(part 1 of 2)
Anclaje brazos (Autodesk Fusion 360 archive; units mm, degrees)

design "Anclaje brazos" references "Anillos_cuerpo_baimax", "pilares_anillos_baimax"
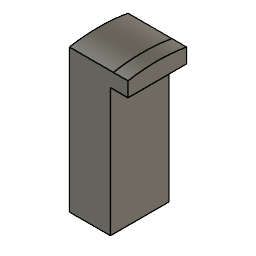
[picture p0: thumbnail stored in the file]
part number: 2026-07-14-14-53-27-253
component_insert "Inserción de componente1"
component_insert "Inserción de componente2"
position "Posición1"
component_insert "Inserción de componente3"
component_insert "Inserción de componente4"
component_insert "Inserción de componente5"
position "Posición2"
sketch "Boceto1" plane through (0, 0, 91.5) normal (0, 0, 1) x axis (1, 0, 0)
  line L1 (1.5, 3) -> (0, 3)
  line L2 (1.5, 0) -> (1.5, 3)
  line L3 (-1.5, 0) -> (1.5, 0)
  line L4 (-1.5, 3) -> (-1.5, 0)
  line L5 (0, 3) -> (-1.5, 3)
  circle C1 centre (0, 1.5) radius 21
  circle C2 centre (0, 1.5) radius 22.75
  circle C3 centre (0, 1.5) radius 5
  point P2 (0, 1.5)
  point P4 (0, 3)
  point P5 (1.5, 3)
  point P6 (1.5, 0)
  point P7 (-1.5, 0)
  point P8 (-1.5, 3)
  concentric C1 C3
  perpendicular L1 L2
  perpendicular L2 L3
  perpendicular L3 L4
  dimension "d1" diameter C3 = 10
  dimension "d2" distance P2 P4 = 1.5
  dimension "d3" distance P4 P5 = 1.5
  dimension "d4" distance P5 P6 = 3
  dimension "d5" distance P6 P7 = 3
  dimension "d6" distance P7 P8 = 3
extrude "Extruir1" new body sketch "Boceto1" profile of L1 L2 L3 L4 L5 along normal blind 7
position "Posición3"
work_plane "PlanoDeObra1" Distance 0
work_plane "PlanoDeObra2" Distance 0
work_plane "PlanoDeObra3" Distance 0
work_plane "PlanoDeObra4" Distance 0
work_plane "PlanoDeObra5" Distance 0
sketch "Boceto2" plane through (-13.1366, 0, 8.8009) normal (-0.8308, 0, 0.5566) x axis (0.5566, 0, 0.8308)
  curve K1 (76.8647, 1.5) -> (74.8126, 1.5)
  curve K2 (75.8387, 7.5) -> (75.8387, -4.5)
  closed curve K3 centre (75.8387, 1.5)
  point P3 (74.8126, 1.5)
  point P4 (76.8647, 1.5)
  point P5 (75.8387, -4.5)
  point P6 (75.8387, 7.5)
  coincident K3 P3
  coincident K3 P4
  coincident K3 P5
  coincident K3 P6
  dimension "d16" = 12
sketch "Boceto3" plane through (-12.068, 0, 51.9927) normal (-0.2261, 0, 0.9741) x axis (0.9741, 0, 0.2261)
  line L1 (52.6699, 3) -> (52.5037, 3)
  line L2 (52.6699, 0) -> (52.5037, 0)
  line L3 (52.6699, 3) -> (52.6699, 0)
  line L4 (53.6699, 1.5) -> (52.6699, 1.5)
  curve K1 (59.1661, 7.4335) -> (59.1661, -4.4335)
  closed curve K2 centre (59.1661, 1.5)
  point P5 (52.6699, 0)
  point P6 (52.6699, 0)
  point P3 (52.6699, 3)
  point P7 (52.6699, 3)
  point P8 (52.6699, 1.5)
  point P11 (59.1661, -4.4335)
  point P12 (59.1661, 7.4335)
  point P9 (53.6699, 1.5)
  coincident P5 P6
  coincident P3 P7
  midpoint L3 P8
  perpendicular L3 L4
  coincident K2 P11
  coincident K2 P12
  dimension "d17" distance P8 P9 = 1
work_plane "PlanoDeObra7" Distance 0
sketch "Boceto4" plane through (37.3705, 0, 0) normal (-1, 0, 0) x axis (0, -1, 0)
  curve K1 (-7.5, 70.5259) -> (4.5, 70.5259)
  curve K2 (-1.5, 67.3726) -> (-1.5, 73.6792)
  closed curve K3 centre (-1.5, 70.5259)
  point P3 (4.5, 70.5259)
  point P4 (-7.5, 70.5259)
  point P5 (-1.5, 73.6792)
  point P6 (-1.5, 67.3726)
  coincident K3 P3
  coincident K3 P4
  coincident K3 P5
  coincident K3 P6
  dimension "d20" distance K3 = 12
sketch "Boceto5" plane through (-0.1048, 0, 0.1825) normal (-0.4982, 0, 0.8671) x axis (0.8671, 0, 0.4982)
  line L1 (53.2165, 0) -> (53.2165, 3)
sketch "Boceto6" plane through (9.9891, 0, -18.2801) normal (-0.4795, 0, 0.8775) x axis (0.8775, 0, 0.4795)
  line L1 (49.7075, 0) -> (49.7075, 3)
  curve K1 (59.1923, 13.5) -> (59.1923, -10.5)
  curve K2 (49.7954, 1.5) -> (68.5892, 1.5)
  closed curve K3 centre (59.1923, 1.5)
  point P5 (59.1923, -10.5)
  point P6 (59.1923, 13.5)
  point P7 (68.5892, 1.5)
  point P8 (49.7954, 1.5)
  coincident K3 P5
  coincident K3 P6
  coincident K3 P7
  coincident K3 P8
  dimension "d36" = 20
sketch "Boceto7" plane through (2.1859, 0, 8.3402) normal (0.2535, 0, 0.9673) x axis (0.9673, 0, -0.2535)
  line L1 (54.1489, 3) -> (54.1489, 0)
  curve K1 (64.3232, 16.5) -> (64.3232, -13.5)
  curve K2 (77.3232, 1.5) -> (51.3232, 1.5)
  closed curve K3 centre (64.3232, 1.5)
  point P5 (64.3232, -13.5)
  point P6 (64.3232, 16.5)
  point P7 (51.3232, 1.5)
  point P8 (77.3232, 1.5)
  coincident K3 P5
  coincident K3 P6
  coincident K3 P7
  coincident K3 P8
  vertical K1
  dimension "d40" distance K3 = 30
  dimension "d41" = 26
work_plane "PlanoDeObra8" Distance 0
sketch "Boceto8" plane through (0, 0, 60.2768) normal (0, 0, 1) x axis (1, 0, 0)
work_plane "PlanoDeObra10" sketch "Boceto4" + "Boceto3"
sketch "Boceto9" plane through (-4.7545, 0, 3.4501) normal (-0.8094, 0, 0.5873) x axis (0, -1, 0)
  curve K1 (-7.5, 80.5735) -> (4.5, 80.5735)
  curve K2 (-1.5, 77.0735) -> (-1.5, 84.0735)
  closed curve K3 centre (-1.5, 80.5735)
  point P3 (4.5, 80.5735)
  point P4 (-7.5, 80.5735)
  point P5 (-1.5, 84.0735)
  point P6 (-1.5, 77.0735)
  coincident K3 P3
  coincident K3 P4
  coincident K3 P5
  coincident K3 P6
  horizontal K1
  dimension "d33" = 7
work_plane "PlanoDeObra12" Distance 0
sketch "Boceto10" plane through (0, 0, 20.5538) normal (0, 0, 1) x axis (1, 0, 0)
  line L1 (64.1747, 1.5) -> (59.5607, 1.5)
  curve K1 (61.8677, 9.5) -> (61.8677, -6.5)
  curve K2 (54.4816, 1.5) -> (69.2538, 1.5)
  closed curve K3 centre (61.8677, 1.5)
  point P5 (61.8677, -6.5)
  point P6 (61.8677, 9.5)
  point P7 (69.2538, 1.5)
  point P8 (54.4816, 1.5)
  point P4 (61.8677, 1.5)
  coincident K3 P5
  coincident K3 P6
  coincident K3 P7
  coincident K3 P8
  midpoint L1 P4
  perpendicular L1 K1
  dimension "d38" distance K3 = 16
  dimension "d39" = 15
work_plane "PlanoDeObra13" Distance 0
sketch "Boceto11" plane through (0, 0, -29.4847) normal (0, 0, 1) x axis (1, 0, 0)
  closed curve K1 centre (63.9334, 1.5)
loft "Solevación1"
work_plane "PlanoDeObra14" AlongDistance 2 ExtraOffset 0
sketch "Boceto12" plane through (52.7171, 0, 38.5545) normal (-0.8072, 0, -0.5903) x axis (-0.5903, 0, 0.8072)
extrude "Extruir2" add of existing geometry blind 2
fillet "Empalme1" radius 1.45
combine "Combinar1"
combine "Combinar2"
sketch "Boceto13" plane through (0, 0, 0) normal (0, 1, 0) x axis (1, 0, 0)
  curve K1 (53.5835, 11.5) -> (53.5662, 8.5)
  line L1 (52.2259, 11.5) -> (53.5835, 11.5)
  line L2 (53.5662, 8.5) -> (52.2037, 8.5)
  curve K2 (53.5662, 8.5) -> (53.5835, 11.5)
  line L3 (52.2037, 8.5) -> (53.5662, 8.5)
  line L4 (53.5835, 11.5) -> (52.2259, 11.5)
  curve K3 (55.2371, 1.5) -> (55.4458, -1.5)
  line L5 (53.8121, 1.5) -> (55.2371, 1.5)
  line L6 (55.4458, -1.5) -> (54.0383, -1.5)
  curve K4 (55.4458, -1.5) -> (55.2371, 1.5)
  line L7 (54.0383, -1.5) -> (55.4458, -1.5)
  line L8 (55.2371, 1.5) -> (53.8121, 1.5)
  curve K5 (36.3076, -71.5) -> (36.2569, -70.5052)
  line L9 (38.0777, -71.5) -> (36.3076, -71.5)
  curve K6 (38.0296, -70.4861) -> (38.0777, -71.5)
  curve K7 (63.9334, 29.4847) -> (38.0296, -70.4861)
  line L10 (54.0473, 29.4847) -> (73.8196, 29.4847)
  curve K8 (63.9334, 29.4847) -> (38.0296, -70.4861)
  curve K9 (38.2035, -68.5) -> (38.0296, -70.4861)
  line L11 (36.4708, -68.5) -> (38.2035, -68.5)
  curve K10 (38.0777, -71.5) -> (38.2035, -68.5)
  line L12 (36.3076, -71.5) -> (38.0777, -71.5)
  line L13 (38.2035, -68.5) -> (36.4708, -68.5)
  line L14 (48.8322, -1.5) -> (55.4458, -1.5)
  line L15 (48.2631, 1.5) -> (55.2371, 1.5)
  line L16 (48.8322, -1.5) -> (48.2631, 1.5)
  line L17 (47.8522, 8.5) -> (53.5662, 8.5)
  line L18 (47.8522, 11.5) -> (47.8522, 8.5)
  line L19 (53.5835, 11.5) -> (47.8522, 11.5)
  line L20 (27.3646, -71.5) -> (38.0777, -71.5)
  line L21 (37.3371, -68.5) -> (37.1927, -71.5)
  line L22 (27.143, -68.5) -> (37.3371, -68.5)
  line L23 (27.143, -68.5) -> (27.3646, -71.5)
  line L24 (54.8106, 1.5) -> (54.7421, -1.5)
  line L25 (54.8106, 1.5) -> (51.7501, 1.5)
  line L26 (48.8322, -1.5) -> (54.7421, -1.5)
  line L27 (48.2631, 1.5) -> (54.8106, 1.5)
  line L28 (52.9047, 11.5) -> (52.885, 8.5)
  line L29 (47.8522, 11.5) -> (52.9047, 11.5)
  line L30 (47.8522, 8.5) -> (52.885, 8.5)
  point P6 (55.4458, -1.5)
  point P19 (55.4458, -1.5)
  point P7 (55.2371, 1.5)
  point P21 (55.2371, 1.5)
  point P2 (53.5662, 8.5)
  point P23 (53.5662, 8.5)
  point P3 (53.5835, 11.5)
  point P26 (53.5835, 11.5)
  point P12 (38.0777, -71.5)
  point P27 (38.0777, -71.5)
  point P29 (37.1927, -71.5)
  point P30 (37.3371, -68.5)
  point P32 (54.7421, -1.5)
  point P33 (54.8106, 1.5)
  point P34 (51.7501, 1.5)
  point P35 (52.885, 8.5)
  point P36 (52.9047, 11.5)
  coincident P6 P19
  parallel L6 L14
  coincident P7 P21
  parallel L5 L15
  coincident P2 P23
  parallel L3 L17
  perpendicular L1 L18
  coincident P3 P26
  perpendicular L18 L19
  coincident P12 P27
  parallel L12 L20
  midpoint L12 P29
  midpoint L11 P30
  parallel L11 L22
  midpoint L7 P32
  coincident L15 P33
  midpoint L15 P34
  midpoint L2 P35
  midpoint L4 P36
extrude "Extruir3" cut sketch "Boceto13" profile of L17 L18 L19 distance 10
extrude "Extruir4" cut sketch "Boceto13" profile of L14 L15 L16 distance 10
extrude "Extruir5" cut sketch "Boceto13" profile of L9 L11 L12 L13 L20 L21 L22 L23 distance 10
copy_paste_bodies "CopiarPegarCuerpos1"
move "Desplazar1"
copy_paste_bodies "CopiarPegarCuerpos2"
move "Desplazar2"
sketch "Boceto14" plane through (0, 0, 68.5) normal (0, 0, 1) x axis (-1, 0, 0)
  curve K1 (-37.3371, 3.0523) -> (-38.2035, 3.2691)
  curve K2 (-38.2035, -6.2691) -> (-37.3371, -6.0523)
  curve K3 (-37.3371, -6.0523) -> (-36.4708, -6.0214)
  curve K4 (-36.4708, -6.0214) -> (-33.2944, -7.0292)
  curve K5 (-32.613, -7.3029) -> (-30.8166, -5.8595)
  line L1 (-30.8166, 2.8595) -> (-30.8166, -5.8595)
  curve K6 (-30.8166, 2.8595) -> (-31.321, 4.0574)
  curve K7 (-31.321, 4.0574) -> (-32.613, 4.3029)
  curve K8 (-33.2944, 4.0292) -> (-36.4708, 3.0214)
  curve K9 (-36.4708, 3.0214) -> (-37.3371, 3.0523)
  line L2 (-36.25, -1.5) -> (-36.75, -1.5)
  line L3 (-33.25, 0.5) -> (-33.25, -1.5)
  line L4 (-33.05, 0.5) -> (-33.25, 0.5)
  line L5 (-36.25, 0.7) -> (-36.25, 0.5)
  line L6 (-36.25, -3.7) -> (-36.25, -3.5)
  line L7 (-33.25, -3.7) -> (-33.25, -3.5)
  line L8 (-33.05, 0.7) -> (-33.05, 0.5)
  line L9 (-33.25, 0.7) -> (-33.05, 0.7)
  line L10 (-36.45, 0.7) -> (-33.25, 0.7)
  line L11 (-36.45, -3.7) -> (-36.45, 0.7)
  line L12 (-33.25, -3.7) -> (-36.45, -3.7)
  line L13 (-33.05, 0.5) -> (-33.05, -3.5)
  line L14 (-33.05, -3.7) -> (-33.25, -3.7)
  line L15 (-33.05, -3.5) -> (-33.05, -3.7)
  arc A1 centre (0, -1.5) radius 38.5 clockwise from (-38.2035, -6.2691) to (-38.2035, 3.2691)
  closed curve K10 centre (-31.321, -1.5)
  closed curve K11 centre (-31.321, -1.5)
  circle C1 centre (0, -1.5) radius 36.75
  circle C2 centre (0, -1.5) radius 36.75
  point P18 (-36.75, -1.5)
  point P19 (-36.25, -1.5)
  point P20 (-33.25, -1.5)
  point P21 (-36.25, 0.5)
  point P22 (-33.25, 0.5)
  point P23 (-36.25, -3.5)
  point P24 (-33.25, -3.5)
  point P25 (-33.05, 0.5)
  point P26 (-33.25, 0.7)
  point P27 (-36.25, 0.7)
  point P28 (-36.25, -3.7)
  point P29 (-33.25, -3.7)
  point P30 (-33.05, -3.5)
  point P31 (-33.05, 0.7)
  point P32 (-36.45, 0.7)
  point P33 (-36.45, -3.7)
  coincident C2 P18
  perpendicular L1 L2
  perpendicular L3 L4
  perpendicular L4 L8
  perpendicular L5 L10
  perpendicular L7 L14
  dimension "d56" distance P18 P19 = 0.5
  dimension "d57" distance P19 P20 = 3
  dimension "d58" distance P19 P21 = 2
  dimension "d59" distance P21 P22 = 3
  dimension "d61" distance P19 P23 = 2
  dimension "d62" distance P22 P24 = 4
  dimension "d63" distance P22 P25 = 0.2
  dimension "d64" distance P22 P26 = 0.2
  dimension "d65" distance P21 P27 = 0.2
  dimension "d68" distance P23 P28 = 0.2
  dimension "d69" distance P24 P29 = 0.2
  dimension "d70" distance P24 P30 = 0.2
  dimension "d71" distance P25 P31 = 0.2
  dimension "d72" distance P26 P32 = 3.2
  dimension "d73" distance P32 P33 = 4.4
extrude "Extruir6" cut sketch "Boceto14" profile of L8 L9 L10 L11 L12 L13 L14 L15 distance 40
extrude "Extruir7" cut of existing geometry blind -0.2
extrude "Extruir8" cut of existing geometry blind -0.2
extrude "Extruir9" cut of existing geometry blind -0.2
extrude "Extruir10" cut of existing geometry blind -0.2
extrude "Extruir11" cut of existing geometry blind -0.2
extrude "Extruir12" cut of existing geometry blind -0.2
sketch "Boceto15" plane through (0, 0, 0) normal (0, 1, 0) x axis (1, 0, 0)
  curve K1 (53.5835, 11.5) -> (53.586, 11.7)
  curve K2 (53.5662, 8.5) -> (53.5835, 11.5)
  curve K3 (53.5665, 8.3) -> (53.5662, 8.5)
  line L1 (52.4857, 8.3) -> (53.5665, 8.3)
  curve K4 (52.8572, 8.5) -> (52.4857, 8.3)
  line L2 (52.2037, 8.5) -> (52.8572, 8.5)
  line L3 (51.3074, 8.5) -> (52.2037, 8.5)
  line L4 (52.8572, 8.5) -> (52.2037, 8.5)
  curve K5 (52.4857, 8.3) -> (52.8572, 8.5)
  line L5 (53.5665, 8.3) -> (52.4857, 8.3)
  curve K6 (53.5662, 8.5) -> (53.5665, 8.3)
  curve K7 (53.5835, 11.5) -> (53.5662, 8.5)
  curve K8 (53.586, 11.7) -> (53.5835, 11.5)
  line L6 (51.416, 11.7) -> (53.586, 11.7)
  line L7 (30.954, -71.7) -> (38.0987, -71.7)
  line L8 (30.954, -71.7) -> (30.8357, -71.8618)
  line L9 (38.0987, -71.7) -> (30.954, -71.7)
  curve K9 (38.0777, -71.5) -> (38.0987, -71.7)
  curve K10 (38.0296, -70.4861) -> (38.0777, -71.5)
  curve K11 (63.9334, 29.4847) -> (38.0296, -70.4861)
  line L10 (54.0473, 29.4847) -> (73.8196, 29.4847)
  curve K12 (63.9334, 29.4847) -> (38.0296, -70.4861)
  curve K13 (38.2035, -68.5) -> (38.0296, -70.4861)
  curve K14 (38.2386, -68.3) -> (38.2035, -68.5)
  line L11 (33.4406, -68.3) -> (38.2386, -68.3)
  line L12 (34.2543, -67.1874) -> (33.4406, -68.3)
  curve K15 (36.45, -67.6695) -> (34.2543, -67.1874)
  line L13 (36.45, -67.4592) -> (36.45, -67.6695)
  curve K16 (34.2543, -67.1874) -> (36.45, -67.6695)
  line L14 (34.2543, -67.1874) -> (33.4406, -68.3)
  line L15 (38.2386, -68.3) -> (33.4406, -68.3)
  curve K17 (38.2035, -68.5) -> (38.2386, -68.3)
  curve K18 (38.0777, -71.5) -> (38.2035, -68.5)
  curve K19 (38.0987, -71.7) -> (38.0777, -71.5)
  curve K20 (36.45, -73.4124) -> (33.05, -72.6307)
  line L16 (36.45, -73.6296) -> (36.45, -73.4124)
  curve K21 (33.05, -72.6307) -> (36.45, -73.4124)
  line L17 (33.05, -72.8531) -> (33.05, -72.6307)
  curve K22 (55.4588, -1.7) -> (55.4458, -1.5)
  line L18 (53.3559, -1.7) -> (55.4588, -1.7)
  curve K23 (55.4458, -1.5) -> (55.4588, -1.7)
  curve K24 (55.2371, 1.5) -> (55.4458, -1.5)
  line L19 (54.8106, 1.5) -> (55.2371, 1.5)
  line L20 (53.8121, 1.5) -> (54.8106, 1.5)
  line L21 (52.2582, 1.5) -> (53.8121, 1.5)
  line L22 (54.734, 1.5) -> (53.8121, 1.5)
  line L23 (55.2371, 1.5) -> (54.734, 1.5)
  curve K25 (55.4458, -1.5) -> (55.2371, 1.5)
  line L24 (55.2371, 1.5) -> (55.4588, -1.7)
  line L25 (55.2715, 0.9996) -> (55.2371, 1.5)
  line L26 (55.2233, 1.7) -> (55.2371, 1.7)
  line L27 (55.2233, 1.7) -> (55.2371, 1.5)
  line L28 (51.3186, 1.7) -> (55.2233, 1.7)
  line L29 (51.3186, 1.4033) -> (51.3186, 1.7)
  line L30 (51.3186, 1.4033) -> (52.2582, 1.5)
  line L31 (50.5573, 8.3) -> (53.5665, 8.3)
  line L32 (50.5573, 9.2223) -> (50.5573, 8.3)
  line L33 (53.5665, 8.3) -> (50.5573, 9.2223)
  point P30 (55.4588, -1.7)
  point P37 (55.4588, -1.7)
  point P32 (55.2371, 1.5)
  point P38 (55.2371, 1.5)
  point P40 (55.2715, 0.9996)
  point P42 (55.2371, 1.5)
  point P35 (52.2582, 1.5)
  point P45 (52.2582, 1.5)
  point P5 (53.5665, 8.3)
  point P46 (53.5665, 8.3)
  point P49 (53.5665, 8.3)
  point P39 (55.2371, 1.7)
  coincident P30 P37
  coincident P32 P38
  coincident K24 P40
  coincident K25 P40
  coincident P32 P42
  parallel L26 L28
  perpendicular L28 L29
  coincident P35 P45
  coincident P5 P46
  parallel L1 L31
  perpendicular L31 L32
  coincident P5 P49
  dimension "d88" distance P38 P39 = 0.2
extrude "Extruir13" cut sketch "Boceto15" profile of L19 L20 L21 L22 L23 L27 L28 L29 L30 distance 120
extrude "Extruir14" cut of existing geometry to an object
extrude "Extruir15" cut of existing geometry to an object
extrude "Extruir16" cut sketch "Boceto15" profile of L1 L5 L31 L32 L33 distance 120
extrude "Extruir17" new body of existing geometry blind 3.2
extrude "Extruir18" cut of existing geometry blind -0.2
extrude "Extruir19" cut of existing geometry blind -4
extrude "Extruir20" cut of existing geometry blind -0.2
extrude "Extruir21" cut of existing geometry blind -0.2
extrude "Extruir22" cut of existing geometry blind -4
extrude "Extruir23" add of existing geometry blind 6
move "Desplazar3"
extrude "Extruir24" add of existing geometry blind 2
sketch "Boceto16" plane through (36.25, 0, 0) normal (1, 0, 0) x axis (0, 1, 0)
  line L1 (3.5, 74.9512) -> (3.5, 65.2)
  curve K1 (3.5, 74.9512) -> (-0.5, 74.9512)
  line L2 (-0.5, 65.2) -> (-0.5, 74.9512)
  line L3 (3.5, 65.2) -> (-0.5, 65.2)
  line L4 (-0.5, 73.9512) -> (-0.5, 74.9512)
  line L5 (3.5, 73.9512) -> (-0.5, 73.9512)
  point P4 (-0.5, 74.9512)
  point P6 (-0.5, 74.9512)
  point P8 (3.5, 73.9512)
  point P7 (-0.5, 73.9512)
  coincident P4 P6
  parallel L2 L4
  coincident L1 P8
  perpendicular L1 L5
  dimension "d113" distance P6 P7 = 1
extrude "Extruir25" add sketch "Boceto16" profile of L1 K1 L2 L4 L5 along normal blind 1
extrude "Extruir26" cut of existing geometry blind -0.5
extrude "Extruir27" add of existing geometry blind 0.3
copy_paste_bodies "CopiarPegarCuerpos3"
move "Desplazar4"
work_plane "PlanoDeObra15" AlongDistance 0 ExtraOffset 0
sketch "Boceto17" plane through (0, 0, -38.5) normal (0, 0, -1) x axis (-1, 0, 0)
offset_faces "CarasDesfase" distance 5
fillet "Empalme2" radius 7
work_plane "PlanoDeObra16" sketch "Boceto17" AlongDistance -3 ExtraOffset 0
sketch "Boceto18" plane through (0, 0, -35.5) normal (0, 0, -1) x axis (-1, 0, 0)
  curve K1 (-50.3733, 42.62) -> (-50.6427, 42.9873)
  curve K2 (-50.6427, 42.9873) -> (-50.3733, 42.62)
  curve K3 (-45.3276, 46.9224) -> (-45.3276, 46.9224)
  circle C1 centre (-48.3943, 40.8173) radius 1.75
  circle C2 centre (-51.1986, 51.5115) radius 1.75
  circle C3 centre (-47.4332, 56.089) radius 1.75
  circle C4 centre (-42.4948, 59.6646) radius 1.75
  circle C5 centre (-36.1301, 60.3304) radius 1.75
  point P6 (-48.3943, 40.8173)
  point P7 (-51.1986, 51.5115)
  point P8 (-47.4332, 56.089)
  point P9 (-42.4948, 59.6646)
  point P10 (-36.1301, 60.3304)
  coincident K2 P6
  coincident K2 P7
  coincident K2 P8
  coincident K2 P9
  coincident K2 P10
  dimension "d127" diameter C1 = 3.5
  dimension "d128" diameter C2 = 3.5
  dimension "d129" diameter C3 = 3.5
  dimension "d130" diameter C4 = 3.5
  dimension "d131" diameter C5 = 3.5
work_plane "PlanoDeObra17" sketch "Boceto18" AlongDistance -4 ExtraOffset 0
sketch "Boceto19" plane through (0, 0, -31.5) normal (0, 0, -1) x axis (-1, 0, 0)
  line L1 (-45.3276, 46.9224) -> (-50.6427, 42.9873)
  curve K1 (-50.3733, 42.62) -> (-50.6427, 42.9873)
  curve K2 (-50.6427, 42.9873) -> (-50.3733, 42.62)
  line L2 (-45.3276, 46.9224) -> (-50.6427, 42.9873)
  curve K3 (-45.3276, 46.9224) -> (-45.3276, 46.9224)
  circle C1 centre (-47.2256, 42.1199) radius 2
  circle C2 centre (-49.6515, 50.6936) radius 2
  circle C3 centre (-46.2588, 54.7916) radius 2
  circle C4 centre (-41.7932, 58.0614) radius 2
  circle C5 centre (-36.7005, 58.676) radius 2
  dimension "d134" diameter C1 = 4
  dimension "d135" diameter C2 = 4
  dimension "d136" diameter C3 = 4
  dimension "d137" diameter C4 = 4
  dimension "d138" diameter C5 = 4
loft "Solevación2" sketch "Boceto19" + "Boceto18"
loft "Solevación3" sketch "Boceto18" + "Boceto19"
loft "Solevación4" sketch "Boceto18" + "Boceto19"
loft "Solevación5" sketch "Boceto18" + "Boceto19"
loft "Solevación6" sketch "Boceto18" + "Boceto19"
fillet "Empalme3" radius 1
fillet "Empalme4" radius 1
fillet "Empalme5" radius 1
fillet "Empalme6" radius 1
fillet "Empalme7" radius 1
extrude "Extruir28" add of existing geometry blind 3
extrude "Extruir29" add of existing geometry blind 3
extrude "Extruir30" add of existing geometry blind 3
extrude "Extruir31" add of existing geometry blind 3
copy_paste_bodies "CopiarPegarCuerpos4"
move "Desplazar5"
mirror "Simetría" mirrorStitchTolerance 0.1
work_plane "PlanoDeObra18" AlongDistance 0 ExtraOffset 0
sketch "Boceto20" plane through (0, -52.25, 0) normal (0, -1, 0) x axis (0, 0, 1)
  line L1 (-21.5, 0) -> (-18.5, 0)
  line L2 (-20, -25) -> (-20, 0)
  line L3 (-20, 25) -> (-20, -25)
  circle C1 centre (-20, -25) radius 12.5
  circle C2 centre (-20, 25) radius 12.5
  point P4 (-20, 0)
  point P5 (-20, -25)
  point P7 (-20, -25)
  point P6 (-20, 25)
  point P8 (-20, 25)
  midpoint L1 P4
  perpendicular L1 L2
  perpendicular L1 L3
  coincident P5 P7
  coincident P6 P8
  dimension "d161" distance P4 P5 = 25
  dimension "d162" distance P5 P6 = 50
  dimension "d163" diameter C1 = 25
  dimension "d164" diameter C2 = 25
extrude "Extruir32" new body sketch "Boceto20" profile of C1 C2 along normal blind 25
move "Desplazar6"
extrude "Extruir33" add of existing geometry blind 25
combine "Combinar3"
combine "Combinar4"
move "Desplazar7"
sketch "Boceto21" plane through (0, 0, 0) normal (1, 0, 0) x axis (0, 1, 0)
  curve K1 (-72.9701, -18.5) -> (-74.0431, -21.5)
  line L1 (-70.3375, -18.5) -> (-72.9701, -18.5)
  curve K2 (-71.4962, -21.5) -> (-70.3375, -18.5)
  line L2 (-74.0431, -21.5) -> (-71.4962, -21.5)
  curve K3 (-87.3448, -21.5) -> (-87.6216, -18.5)
  line L3 (-85.5239, -21.5) -> (-87.3448, -21.5)
  curve K4 (-85.8114, -18.5) -> (-85.5239, -21.5)
  line L4 (-87.6216, -18.5) -> (-85.8114, -18.5)
  curve K5 (-91.0848, -11.5) -> (-90.635, -8.5)
  line L5 (-89.2774, -11.5) -> (-91.0848, -11.5)
  curve K6 (-88.8115, -8.5) -> (-89.2774, -11.5)
  line L6 (-90.635, -8.5) -> (-88.8115, -8.5)
  curve K7 (-79.9495, -8.5) -> (-78.4871, -11.5)
  line L7 (-77.6312, -8.5) -> (-79.9495, -8.5)
  curve K8 (-76.0786, -11.5) -> (-77.6312, -8.5)
  line L8 (-78.4871, -11.5) -> (-76.0786, -11.5)
  line L9 (-67.25, -3.5) -> (-67.25, -28.5)
  line L10 (-117.25, -28.5) -> (-117.25, -3.5)
  line L11 (-67.25, -8.5) -> (-77.6312, -8.5)
  line L12 (-67.25, -11.5) -> (-76.0786, -11.5)
  line L13 (-67.25, -18.5) -> (-70.3375, -18.5)
  line L14 (-67.25, -21.5) -> (-71.4962, -21.5)
  point P16 (-77.6312, -8.5)
  point P22 (-77.6312, -8.5)
  point P23 (-67.25, -8.5)
  point P17 (-76.0786, -11.5)
  point P24 (-76.0786, -11.5)
  point P25 (-67.25, -11.5)
  point P4 (-70.3375, -18.5)
  point P26 (-70.3375, -18.5)
  point P27 (-67.25, -18.5)
  point P5 (-71.4962, -21.5)
  point P28 (-71.4962, -21.5)
  point P29 (-67.25, -21.5)
  coincident P16 P22
  coincident L9 P23
  perpendicular L9 L11
  coincident P17 P24
  coincident L9 P25
  perpendicular L9 L12
  coincident P4 P26
  coincident L9 P27
  perpendicular L9 L13
  coincident P5 P28
  coincident L9 P29
  perpendicular L9 L14
extrude "Extruir34" cut sketch "Boceto21" profile of K1 L1 K2 L2 K7 L7 K8 L8 L9 L11 L12 L13 L14 along normal blind 100
sketch "Boceto22" plane through (0, 0, -21.5) normal (0, 0, 1) x axis (-1, 0, 0)
  line L1 (-13.775, 87.3448) -> (-13.775, 85.5239)
  line L2 (-36.225, 71.4962) -> (-36.225, 74.0431)
  line L3 (-13.775, 71.4962) -> (-36.225, 71.4962)
  line L4 (-13.775, 74.0431) -> (-13.775, 71.4962)
  line L5 (-33.7296, 74.0431) -> (-13.775, 74.0431)
  line L6 (-13.775, 85.5239) -> (-13.775, 74.0431)
  arc A1 centre (0, 38.5) radius 49 clockwise from (-33.7296, 74.0431) to (-13.775, 85.5239)
  arc A2 centre (0, 38.5) radius 50.75 clockwise from (-36.225, 74.0431) to (-13.775, 87.3448)
  point P9 (-13.775, 74.0431)
  point P10 (-13.775, 74.0431)
  point P2 (-13.775, 85.5239)
  point P11 (-13.775, 85.5239)
  coincident P9 P10
  coincident P2 P11
extrude "Extruir35" cut sketch "Boceto22" profile of A1 L5 L6 to an object
extrude "Extruir36" cut of existing geometry blind -6
extrude "Extruir37" cut of existing geometry blind -1
extrude "Extruir38" cut of existing geometry blind -3
extrude "Extruir39" cut of existing geometry blind -1
extrude "Extruir40" cut of existing geometry blind -1
extrude "Extruir41" cut of existing geometry blind -3
sketch "Boceto23" plane through (0, 0, -11.5) normal (0, 0, 1) x axis (-1, 0, 0)
  line L1 (-13.3381, 91.0848) -> (-13.3381, 89.2774)
  line L2 (-36.6619, 76.0786) -> (-36.6619, 78.4871)
  line L3 (-13.3381, 76.0786) -> (-36.6619, 76.0786)
  line L4 (-13.3381, 78.4871) -> (-13.3381, 76.0786)
  line L5 (-34.0189, 78.4871) -> (-13.3381, 78.4871)
  line L6 (-13.3381, 78.4871) -> (-13.3381, 89.2774)
  arc A1 centre (0, 38.5) radius 52.5 clockwise from (-34.0189, 78.4871) to (-13.3381, 89.2774)
  arc A2 centre (0, 38.5) radius 54.25 clockwise from (-36.6619, 78.4871) to (-13.3381, 91.0848)
  point P2 (-13.3381, 89.2774)
  point P10 (-13.3381, 89.2774)
  point P9 (-13.3381, 78.4871)
  point P11 (-13.3381, 78.4871)
  coincident P2 P10
  coincident P9 P11
extrude "Extruir42" cut sketch "Boceto23" profile of A1 L5 L6 to an object
extrude "Extruir43" cut of existing geometry blind -0.2
extrude "Extruir44" cut of existing geometry blind -0.2
extrude "Extruir45" cut of existing geometry blind -0.2
extrude "Extruir46" cut of existing geometry blind -0.2
extrude "Extruir47" cut of existing geometry blind -3
extrude "Extruir48" cut of existing geometry blind -3
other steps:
base_feature "Elemento base1"
base_feature "Elemento base2"
base_feature "Elemento base3"
base_feature "Elemento base4"

design "Anillos_cuerpo_baimax"
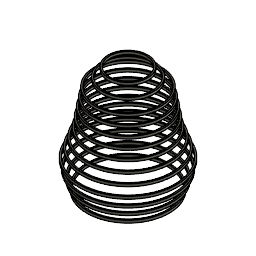
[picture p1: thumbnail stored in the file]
part number: 2026-07-06-18-36-34-739
parameter "d_1" = 112
parameter "d_1_int" = 108.5 (= "d_1 - 3.5 mm")
parameter "h_1" = -10
parameter "d_2" = 108.5
parameter "d_2_int" = 105 (= "d_2 - 3.5 mm")
parameter "h_2" = 10
parameter "h_3" = -20
parameter "h_4" = 20
parameter "h_5" = -30
parameter "h_6" = 30
parameter "h_7" = 40
parameter "d_3" = 105 (= "d_2_int")
parameter "d_3_int" = 101.5 (= "d_3 - 3.5 mm")
parameter "d_4" = 101.5 (= "d_3_int")
parameter "d_4_int" = 98 (= "d_4 - 3.5 mm")
parameter "d_5" = 98 (= "d_4_int")
parameter "d_5_int" = 94.5 (= "d_5 - 3.5 mm")
parameter "d_6" = 94.5 (= "d_5_int")
parameter "d_6_int" = 91 (= "d_6 - 3.5 mm")
parameter "d_7" = 91 (= "d_6_int")
parameter "d_7_int" = 87.5 (= "d_7 - 3.5 mm")
parameter "d_8" = 87.5 (= "d_7_int")
parameter "d_8_int" = 84 (= "d_8 - 3.5 mm")
parameter "h_8" = 50
parameter "h_9" = 60
parameter "h_10" = 70
parameter "h_11" = 110
parameter "h_12" = 120
parameter "h_13" = 130
parameter "h_14" = 140
parameter "h_15" = 80
parameter "d_9" = 84 (= "d_8_int")
parameter "d_9_int" = 80.5 (= "d_9 - 3.5 mm")
parameter "d_10" = 80.5 (= "d_9_int")
parameter "d_10_int" = 77 (= "d_10 - 3.5 mm")
parameter "d_11" = 77 (= "d_10_int")
parameter "d_11_int" = 73.5 (= "d_11 - 3.5 mm")
parameter "d_12" = 73.5 (= "d_11_int")
parameter "d_12_int" = 70 (= "d_12 - 3.5 mm")
parameter "d_13" = 70 (= "d_12_int")
parameter "d_13_int" = 66.5 (= "d_13 - 3.5 mm")
parameter "d_14" = 66.5 (= "d_13_int")
parameter "d_14_int" = 63 (= "d_14 - 3.5 mm")
parameter "d_15" = 63 (= "d_14_int")
parameter "d_15_int" = 59.5 (= "d_15 - 3.5 mm")
parameter "d_16" = 59.5 (= "d_15_int")
parameter "d_16_int" = 56 (= "d_16 - 3.5 mm")
parameter "h_16" = 160
parameter "h_17" = 170
parameter "h_18" = 180
parameter "h_19" = 90
parameter "h_20" = 200
parameter "d_17" = 56 (= "d_16_int")
parameter "d_17_int" = 52.5 (= "d_17 - 3.5 mm")
parameter "d_18" = 52.5 (= "d_17_int")
parameter "d_18_int" = 49 (= "d_18 - 3.5 mm")
parameter "d_19" = 49 (= "d_18_int")
parameter "d_19_int" = 45.5 (= "d_19 - 3.5 mm")
parameter "d_20" = 45.5 (= "d_19_int")
parameter "d_20_int" = 42 (= "d_20 - 3.5 mm")
parameter "d_21" = 42 (= "d_20_int")
parameter "d_21_int" = 38.5 (= "d_21 - 3.5 mm")
parameter "h_21" = 210
parameter "h_22" = 220
parameter "h_23" = 295
parameter "h_24" = 295
parameter "h_25" = 300
parameter "h_26" = 290
parameter "h_27" = 305
parameter "h_28" = 285
parameter "d_22" = 38.5 (= "d_21_int")
parameter "d_22_int" = 35 (= "d_22 - 3.5 mm")
parameter "d_23" = 35 (= "d_22_int")
parameter "d_23_int" = 31.5 (= "d_23 - 3.5 mm")
parameter "d_24" = 31.5 (= "d_23_int")
parameter "d_24_int" = 28 (= "d_24 - 3.5 mm")
parameter "d_25" = 28 (= "d_24_int")
parameter "d_25_int" = 24.5 (= "d_25 - 3.5 mm")
parameter "d_26" = 24.5 (= "d_25_int")
parameter "d_26_int" = 21 (= "d_26 - 3.5 mm")
parameter "d_27" = 21 (= "d_26_int")
parameter "d_27_int" = 17.5 (= "d_27 - 3.5 mm")
parameter "d_28" = 17.5 (= "d_27_int")
parameter "d_28_int" = 14 (= "d_28 - 3.5 mm")
parameter "d_29" = 14 (= "d_28_int")
parameter "d_29_int" = 10.5 (= "d_29 - 3.5 mm")
sketch "Boceto1" plane through (0, 0, 0) normal (0, 1, 0) x axis (1, 0, 0)
  circle C1 centre (0, 0) radius 56
  circle C2 centre (0, 0) radius 54.25
  point P1 (0, 0)
  point P2 (0, 0)
  coincident P1 P2
  concentric C1 C2
  dimension "d1" diameter C1 = 112 (= "d_1")
  dimension "d2" diameter C2 = 108.5 (= "d_1_int")
extrude "Extruir1" new body sketch "Boceto1" along normal blind 3
work_plane "PlanoDeObra2" AlongDistance -10 (= "h_1")
sketch "Boceto3" plane through (0, -10, 0) normal (0, 1, 0) x axis (1, 0, 0)
  circle C1 centre (0, 0) radius 54.25
  circle C2 centre (0, 0) radius 52.5
  point P1 (0, 0)
  point P2 (0, 0)
  coincident P1 P2
  concentric C1 C2
  dimension "d12" diameter C2 = 105 (= "d_2_int")
  dimension "d13" diameter C1 = 108.5 (= "d_2")
extrude "Extruir2" new body sketch "Boceto3" along normal blind 3
work_plane "PlanoDeObra3" AlongDistance 0
work_plane "PlanoDeObra4" AlongDistance 10 (= "h_2")
sketch "Boceto4" plane through (0, 10, 0) normal (0, 1, 0) x axis (1, 0, 0)
  circle C1 centre (0, 0) radius 52.5
  circle C2 centre (0, 0) radius 50.75
  point P1 (0, 0)
  point P2 (0, 0)
  point P3 (0, 0)
  coincident P1 P2
  coincident P1 P3
  dimension "d26" diameter C1 = 105 (= "d_3")
  dimension "d27" diameter C2 = 101.5 (= "d_3_int")
extrude "Extruir3" new body sketch "Boceto4" along normal blind 3
work_plane "PlanoDeObra5" AlongDistance -20 (= "h_3")
sketch "Boceto5" plane through (0, -20, 0) normal (0, 1, 0) x axis (1, 0, 0)
  circle C1 centre (0, 0) radius 50.75
  circle C2 centre (0, 0) radius 49
  point P1 (0, 0)
  point P2 (0, 0)
  point P3 (0, 0)
  coincident P1 P2
  coincident P1 P3
  dimension "d41" diameter C1 = 101.5 (= "d_4")
  dimension "d42" diameter C2 = 98 (= "d_4_int")
extrude "Extruir4" new body sketch "Boceto5" along normal blind 3
work_plane "PlanoDeObra6" AlongDistance 20 (= "h_4")
sketch "Boceto6" plane through (0, 20, 0) normal (0, 1, 0) x axis (1, 0, 0)
  circle C1 centre (0, 0) radius 49
  circle C2 centre (0, 0) radius 47.25
  point P1 (0, 0)
  point P2 (0, 0)
  coincident P1 P2
  concentric C1 C2
  dimension "d46" diameter C1 = 98 (= "d_5")
  dimension "d47" diameter C2 = 94.5 (= "d_5_int")
extrude "Extruir5" new body sketch "Boceto6" along normal blind 3
work_plane "PlanoDeObra7" AlongDistance -30 (= "h_5")
sketch "Boceto7" plane through (0, -30, 0) normal (0, 1, 0) x axis (1, 0, 0)
  circle C1 centre (0, 0) radius 47.25
  circle C2 centre (0, 0) radius 45.5
  point P1 (0, 0)
  point P2 (0, 0)
  coincident P1 P2
  concentric C1 C2
  dimension "d51" diameter C1 = 94.5 (= "d_6")
  dimension "d52" diameter C2 = 91 (= "d_6_int")
extrude "Extruir6" new body sketch "Boceto7" along normal blind 3
work_plane "PlanoDeObra8" AlongDistance 30 (= "h_6")
sketch "Boceto9" plane through (0, 30, 0) normal (0, 1, 0) x axis (1, 0, 0)
  circle C1 centre (0, 0) radius 45.5
  circle C2 centre (0, 0) radius 43.75
  point P1 (0, 0)
  point P2 (0, 0)
  point P3 (0, 0)
  coincident P1 P2
  coincident P1 P3
  dimension "d56" diameter C1 = 91 (= "d_7")
  dimension "d57" diameter C2 = 87.5 (= "d_7_int")
extrude "Extruir7" new body sketch "Boceto9" along normal blind 3
work_plane "PlanoDeObra9" AlongDistance 40 (= "h_7")
sketch "Boceto10" plane through (0, 40, 0) normal (0, 1, 0) x axis (1, 0, 0)
  circle C1 centre (0, 0) radius 43.75
  circle C2 centre (0, 0) radius 42
  point P1 (0, 0)
  point P2 (0, 0)
  coincident P1 P2
  concentric C1 C2
  dimension "d61" diameter C1 = 87.5 (= "d_8")
  dimension "d62" diameter C2 = 84 (= "d_8_int")
extrude "Extruir8" new body sketch "Boceto10" along normal blind 3
work_plane "PlanoDeObra10" AlongDistance 50 (= "h_8")
sketch "Boceto11" plane through (0, 50, 0) normal (0, 1, 0) x axis (1, 0, 0)
  circle C1 centre (0, 0) radius 42
  circle C2 centre (0, 0) radius 40.25
  point P1 (0, 0)
  point P2 (0, 0)
  coincident P1 P2
  concentric C1 C2
  dimension "d90" diameter C1 = 84 (= "d_9")
  dimension "d91" diameter C2 = 80.5 (= "d_9_int")
extrude "Extruir9" new body sketch "Boceto11" along normal blind 3
work_plane "PlanoDeObra11" AlongDistance 60 (= "h_9")
sketch "Boceto12" plane through (0, 60, 0) normal (0, 1, 0) x axis (1, 0, 0)
  circle C1 centre (0, 0) radius 40.25
  circle C2 centre (0, 0) radius 38.5
  point P1 (0, 0)
  point P2 (0, 0)
  point P3 (0, 0)
  coincident P1 P2
  coincident P1 P3
  dimension "d95" diameter C1 = 80.5 (= "d_10")
  dimension "d96" diameter C2 = 77 (= "d_10_int")
extrude "Extruir10" new body sketch "Boceto12" along normal blind 3
work_plane "PlanoDeObra12" AlongDistance 70 (= "h_10")
sketch "Boceto13" plane through (0, 70, 0) normal (0, 1, 0) x axis (1, 0, 0)
  circle C1 centre (0, 0) radius 38.5
  circle C2 centre (0, 0) radius 36.75
  point P1 (0, 0)
  point P2 (0, 0)
  point P3 (0, 0)
  coincident P1 P2
  coincident P1 P3
  dimension "d100" diameter C1 = 77 (= "d_11")
  dimension "d101" diameter C2 = 73.5 (= "d_11_int")
extrude "Extruir11" new body sketch "Boceto13" along normal blind 3
work_plane "PlanoDeObra13" AlongDistance 110 (= "h_11")
sketch "Boceto14" plane through (0, 110, 0) normal (0, 1, 0) x axis (1, 0, 0)
  circle C1 centre (0, 0) radius 36.75
  circle C2 centre (0, 0) radius 35
  point P1 (0, 0)
  point P2 (0, 0)
  coincident P1 P2
  concentric C1 C2
  dimension "d105" diameter C1 = 73.5 (= "d_12")
  dimension "d106" diameter C2 = 70 (= "d_12_int")
work_plane "PlanoDeObra14" AlongDistance 120 (= "h_12")
sketch "Boceto15" plane through (0, 120, 0) normal (0, 1, 0) x axis (1, 0, 0)
  circle C1 centre (0, 0) radius 35
  circle C2 centre (0, 0) radius 33.25
  point P1 (0, 0)
  point P2 (0, 0)
  coincident P1 P2
  concentric C1 C2
  dimension "d110" diameter C1 = 70 (= "d_13")
  dimension "d111" diameter C2 = 66.5 (= "d_13_int")
work_plane "PlanoDeObra15" AlongDistance 130 (= "h_13")
sketch "Boceto16" plane through (0, 130, 0) normal (0, 1, 0) x axis (1, 0, 0)
  circle C1 centre (0, 0) radius 33.25
  circle C2 centre (0, 0) radius 31.5
  point P1 (0, 0)
  point P2 (0, 0)
  coincident P1 P2
  concentric C1 C2
  dimension "d115" diameter C1 = 66.5 (= "d_14")
  dimension "d116" diameter C2 = 63 (= "d_14_int")
work_plane "PlanoDeObra17" AlongDistance 140 (= "h_14")
sketch "Boceto17" plane through (0, 140, 0) normal (0, 1, 0) x axis (1, 0, 0)
  circle C1 centre (0, 0) radius 31.5
  circle C2 centre (0, 0) radius 29.75
  point P1 (0, 0)
  point P2 (0, 0)
  point P3 (0, 0)
  coincident P1 P2
  coincident P1 P3
  dimension "d121" diameter C1 = 63 (= "d_15")
  dimension "d122" diameter C2 = 59.5 (= "d_15_int")
work_plane "PlanoDeObra18" AlongDistance 80 (= "h_15")
sketch "Boceto18" plane through (0, 80, 0) normal (0, 1, 0) x axis (1, 0, 0)
  circle C1 centre (0, 0) radius 29.75
  circle C2 centre (0, 0) radius 28
  point P1 (0, 0)
  point P2 (0, 0)
  point P3 (0, 0)
  coincident P1 P2
  coincident P1 P3
  dimension "d126" diameter C1 = 59.5 (= "d_16")
  dimension "d127" diameter C2 = 56 (= "d_16_int")
extrude "Extruir16" new body sketch "Boceto18" along normal blind 3
work_plane "PlanoDeObra19" AlongDistance 160 (= "h_16")
sketch "Boceto19" plane through (0, 160, 0) normal (0, 1, 0) x axis (1, 0, 0)
  circle C1 centre (0, 0) radius 28
  circle C2 centre (0, 0) radius 26.25
  point P1 (0, 0)
  point P2 (0, 0)
  coincident P1 P2
  concentric C1 C2
  dimension "d162" diameter C1 = 56 (= "d_17")
  dimension "d163" diameter C2 = 52.5 (= "d_17_int")
work_plane "PlanoDeObra20" AlongDistance 170 (= "h_17")
sketch "Boceto20" plane through (0, 170, 0) normal (0, 1, 0) x axis (1, 0, 0)
  circle C1 centre (0, 0) radius 26.25
  circle C2 centre (0, 0) radius 24.5
  point P1 (0, 0)
  point P2 (0, 0)
  coincident P1 P2
  concentric C1 C2
  dimension "d167" diameter C1 = 52.5 (= "d_18")
  dimension "d168" diameter C2 = 49 (= "d_18_int")
work_plane "PlanoDeObra21" AlongDistance 180 (= "h_18")
sketch "Boceto21" plane through (0, 180, 0) normal (0, 1, 0) x axis (1, 0, 0)
  circle C1 centre (0, 0) radius 24.5
  circle C2 centre (0, 0) radius 22.75
  point P1 (0, 0)
  point P2 (0, 0)
  point P3 (0, 0)
  coincident P1 P2
  coincident P1 P3
  dimension "d172" diameter C1 = 49 (= "d_19")
  dimension "d173" diameter C2 = 45.5 (= "d_19_int")
work_plane "PlanoDeObra22" AlongDistance 90 (= "h_19")
sketch "Boceto22" plane through (0, 90, 0) normal (0, 1, 0) x axis (1, 0, 0)
  circle C1 centre (0, 0) radius 22.75
  circle C2 centre (0, 0) radius 21
  point P1 (0, 0)
  point P2 (0, 0)
  point P3 (0, 0)
  coincident P1 P2
  coincident P1 P3
  dimension "d177" diameter C1 = 45.5 (= "d_20")
  dimension "d178" diameter C2 = 42 (= "d_20_int")
extrude "Extruir20" new body sketch "Boceto22" along normal blind 3
work_plane "PlanoDeObra24" AlongDistance 200 (= "h_20")
sketch "Boceto24" plane through (0, 200, 0) normal (0, 1, 0) x axis (1, 0, 0)
  circle C1 centre (0, 0) radius 21
  circle C2 centre (0, 0) radius 19.25
  point P1 (0, 0)
  point P2 (0, 0)
  point P3 (0, 0)
  coincident P1 P2
  coincident P1 P3
  dimension "d187" diameter C1 = 42 (= "d_21")
  dimension "d188" diameter C2 = 38.5 (= "d_21_int")
work_plane "PlanoDeObra25" AlongDistance 210 (= "h_21")
sketch "Boceto25" plane through (0, 210, 0) normal (0, 1, 0) x axis (1, 0, 0)
  circle C1 centre (0, 0) radius 19.25
  circle C2 centre (0, 0) radius 17.5
  point P1 (0, 0)
  point P2 (0, 0)
  coincident P1 P2
  concentric C1 C2
  dimension "d220" diameter C1 = 38.5 (= "d_22")
  dimension "d221" diameter C2 = 35 (= "d_22_int")
work_plane "PlanoDeObra26" AlongDistance 220 (= "h_22")
sketch "Boceto26" plane through (0, 220, 0) normal (0, 1, 0) x axis (1, 0, 0)
  circle C1 centre (0, 0) radius 17.5
  circle C2 centre (0, 0) radius 15.75
  point P1 (0, 0)
  point P2 (0, 0)
  coincident P1 P2
  concentric C1 C2
  dimension "d225" diameter C1 = 35 (= "d_23")
  dimension "d226" diameter C2 = 31.5 (= "d_23_int")
work_plane "PlanoDeObra28" AlongDistance 295 (= "h_23")
sketch "Boceto27" plane through (0, 295, 0) normal (0, 1, 0) x axis (1, 0, 0)
  circle C1 centre (0, 0) radius 15.75
  circle C2 centre (0, 0) radius 14
  point P1 (0, 0)
  point P2 (0, 0)
  coincident P1 P2
  concentric C1 C2
  dimension "d231" diameter C1 = 31.5 (= "d_24")
  dimension "d232" diameter C2 = 28 (= "d_24_int")
work_plane "PlanoDeObra29" AlongDistance 295 (= "h_24")
sketch "Boceto28" plane through (0, 295, 0) normal (0, 1, 0) x axis (1, 0, 0)
  circle C1 centre (0, 0) radius 14
  circle C2 centre (0, 0) radius 12.25
  point P1 (0, 0)
  point P2 (0, 0)
  point P3 (0, 0)
  coincident P1 P2
  coincident P1 P3
  dimension "d236" diameter C1 = 28 (= "d_25")
  dimension "d237" diameter C2 = 24.5 (= "d_25_int")
work_plane "PlanoDeObra30" AlongDistance 300 (= "h_25")
sketch "Boceto29" plane through (0, 300, 0) normal (0, 1, 0) x axis (1, 0, 0)
  circle C1 centre (0, 0) radius 12.25
  circle C2 centre (0, 0) radius 10.5
  point P1 (0, 0)
  point P2 (0, 0)
  coincident P1 P2
  concentric C1 C2
  dimension "d241" diameter C1 = 24.5 (= "d_26")
  dimension "d242" diameter C2 = 21 (= "d_26_int")
work_plane "PlanoDeObra31" AlongDistance 290 (= "h_26")
sketch "Boceto30" plane through (0, 290, 0) normal (0, 1, 0) x axis (1, 0, 0)
  circle C1 centre (0, 0) radius 10.5
  circle C2 centre (0, 0) radius 8.75
  point P1 (0, 0)
  point P2 (0, 0)
  point P3 (0, 0)
  coincident P1 P2
  coincident P1 P3
  dimension "d246" diameter C1 = 21 (= "d_27")
  dimension "d247" diameter C2 = 17.5 (= "d_27_int")
work_plane "PlanoDeObra32" AlongDistance 305 (= "h_27")
sketch "Boceto31" plane through (0, 305, 0) normal (0, 1, 0) x axis (1, 0, 0)
  circle C1 centre (0, 0) radius 8.75
  circle C2 centre (0, 0) radius 7
  point P1 (0, 0)
  point P2 (0, 0)
  coincident P1 P2
  concentric C1 C2
  dimension "d251" diameter C1 = 17.5 (= "d_28")
  dimension "d252" diameter C2 = 14 (= "d_28_int")
work_plane "PlanoDeObra33" AlongDistance 285 (= "h_28")
sketch "Boceto32" plane through (0, 285, 0) normal (0, 1, 0) x axis (1, 0, 0)
  circle C1 centre (0, 0) radius 7
  circle C2 centre (0, 0) radius 5.25
  point P1 (0, 0)
  point P2 (0, 0)
  coincident P1 P2
  concentric C1 C2
  dimension "d256" diameter C1 = 14 (= "d_29")
  dimension "d257" diameter C2 = 10.5 (= "d_29_int")
sketch "Boceto33" plane through (0, 0, 0) normal (0, 0, 1) x axis (1, 0, 0)
  line L1 (47.25, -30) -> (45.5, -30)
  line L2 (45.5, -27) -> (47.25, -27)
  line L3 (50.75, -20) -> (49, -20)
  line L4 (49, -17) -> (50.75, -17)
  line L5 (54.25, -10) -> (52.5, -10)
  line L6 (52.5, -7) -> (54.25, -7)
  line L7 (56, 0) -> (54.25, 0)
  line L8 (54.25, 3) -> (56, 3)
  line L9 (52.5, 10) -> (50.75, 10)
  line L10 (50.75, 13) -> (52.5, 13)
  line L11 (49, 20) -> (47.25, 20)
  line L12 (47.25, 23) -> (49, 23)
  line L13 (45.5, 30) -> (43.75, 30)
  line L14 (43.75, 33) -> (45.5, 33)
  line L15 (43.75, 40) -> (42, 40)
  line L16 (42, 43) -> (43.75, 43)
  line L17 (42, 50) -> (40.25, 50)
  line L18 (40.25, 53) -> (42, 53)
  line L19 (40.25, 60) -> (38.5, 60)
  line L20 (38.5, 63) -> (40.25, 63)
  line L21 (38.5, 70) -> (36.75, 70)
  line L22 (36.75, 73) -> (38.5, 73)
  line L23 (29.75, 80) -> (28, 80)
  line L24 (28, 83) -> (29.75, 83)
  line L25 (22.75, 90) -> (21, 90)
  line L26 (21, 93) -> (22.75, 93)
  line L27 (45.5, -30) -> (47.25, -30)
  line L28 (45.5, -27) -> (45.5, -30)
  line L29 (49, -20) -> (50.75, -20)
  line L30 (49, -17) -> (49, -20)
  line L31 (50.75, -17) -> (49, -17)
  line L32 (52.5, -10) -> (54.25, -10)
  line L33 (52.5, -10) -> (54.25, -10)
  line L34 (52.5, -7) -> (52.5, -10)
  line L35 (54.25, 0) -> (56, 0)
  line L36 (54.25, 0) -> (56, 0)
  line L37 (54.25, 3) -> (54.25, 0)
  line L38 (50.75, 10) -> (52.5, 10)
  line L39 (50.75, 13) -> (50.75, 10)
  line L40 (47.25, 20) -> (49, 20)
  line L41 (43.75, 30) -> (45.5, 30)
  line L42 (43.75, 33) -> (43.75, 30)
  line L43 (42, 40) -> (43.75, 40)
  line L44 (42, 43) -> (42, 40)
  line L45 (40.25, 50) -> (42, 50)
  line L46 (38.5, 60) -> (40.25, 60)
  line L47 (38.5, 63) -> (40.25, 63)
  line L48 (36.75, 70) -> (38.5, 70)
  line L49 (36.75, 73) -> (36.75, 70)
  line L50 (38.5, 60) -> (38.5, 63)
  line L51 (40.25, 53) -> (40.25, 50)
  line L52 (38.5, 73) -> (36.75, 75)
  line L53 (28, 80) -> (29.75, 80)
  line L54 (29.75, 83) -> (28, 85)
  line L55 (21, 90) -> (22.75, 90)
  line L56 (21, 93) -> (21, 90)
  line L57 (28, 83) -> (28, 80)
  line L58 (47.25, 23) -> (47.25, 20)
  line L59 (17, 88) -> (17, 90)
  line L60 (41.5, -32) -> (41.5, -25)
  line L61 (2, 90) -> (2, 95)
  line L62 (17, 90) -> (2, 90)
  line L63 (2, 100) -> (2, 95)
  line L64 (5, 100) -> (2, 100)
  line L65 (5, 96) -> (5, 100)
  line L66 (41.5, -37) -> (41.5, -32)
  line L67 (44.5, -37) -> (41.5, -37)
  line L68 (45.5, -37) -> (44.5, -37)
  line L69 (47.25, -38.2302) -> (47.25, -30)
  line L70 (47.25, -37) -> (45.5, -37)
  arc A1 centre (-131.6173, -3.3783) radius 174.4624 clockwise from (17, 88) to (41.5, -25)
  arc A2 centre (-12.1249, 48.1252) radius 54.4955 clockwise from (22.75, 90) to (29.75, 83)
  arc A3 centre (19.2917, 57.9584) radius 24.3969 clockwise from (29.75, 80) to (38.5, 73)
  arc A4 centre (-26.7489, 49.969) radius 68.2544 clockwise from (38.5, 70) to (40.25, 63)
  arc A5 centre (-76.2927, 27.1457) radius 121.0852 clockwise from (40.25, 60) to (42, 53)
  arc A6 centre (22.875, 41.5) radius 20.9289 clockwise from (42, 50) to (43.75, 43)
  arc A7 centre (-1.5, 24.9688) radius 47.6812 clockwise from (43.75, 40) to (45.5, 33)
  arc A8 centre (19.0393, 12.3947) radius 31.7823 clockwise from (45.5, 30) to (49, 23)
  arc A9 centre (-15.6248, -16.6874) radius 74.3124 clockwise from (49, 20) to (52.5, 13)
  arc A10 centre (40.625, -0.3125) radius 15.7278 clockwise from (52.5, 10) to (56, 3)
  arc A11 centre (21.7396, 4.8464) radius 34.6015 clockwise from (56, 0) to (54.25, -7)
  arc A12 centre (24.9327, 0.2836) radius 31.0686 clockwise from (54.25, -10) to (50.75, -17)
  arc A13 centre (-15.8334, 8.9167) radius 72.5915 clockwise from (50.75, -20) to (47.25, -27)
  arc A14 centre (4.1403, 36.9029) radius 59.1033 clockwise from (5, 96) to (22.75, 93)
  point P52 (28, 85)
  point P50 (36.75, 75)
  point P84 (47.25, -37)
  point P2 (47.25, -30)
  point P3 (47.25, -27)
  point P28 (45.5, -30)
  point P8 (56, 0)
  point P35 (54.25, 0)
  point P10 (52.5, 10)
  point P37 (50.75, 10)
  point P12 (49, 20)
  point P39 (47.25, 20)
  point P14 (45.5, 30)
  point P40 (43.75, 30)
  point P18 (42, 50)
  point P44 (40.25, 50)
  point P22 (38.5, 70)
  point P47 (36.75, 70)
  horizontal L1
  perpendicular L2 L28
  perpendicular L4 L30
  perpendicular L6 L34
  perpendicular L8 L37
  perpendicular L10 L39
  perpendicular L14 L42
  perpendicular L16 L44
  perpendicular L22 L49
  perpendicular L19 L50
  perpendicular L18 L51
  perpendicular L26 L56
  perpendicular L24 L57
  perpendicular L12 L58
  coincident P52 A2
  coincident P50 A3
  perpendicular L59 L62
  perpendicular L63 L64
  perpendicular L66 L67
  perpendicular L27 L69
  coincident L69 P84
  perpendicular L69 L70
  dimension "d262" distance P2 P3 = 3
  dimension "d263" distance P2 P28 = 1.75
  dimension "d272" distance P8 P35 = 1.75
  dimension "d275" distance P10 P37 = 1.75
  dimension "d280" distance P12 P39 = 1.75
  dimension "d285" distance P14 P40 = 1.75
  dimension "d288" distance P18 P44 = 1.75
  dimension "d291" distance P22 P47 = 1.75
sketch "Boceto34" plane through (0, 93, 0) normal (0, 1, 0) x axis (-1, 0, 0)
  line L1 (-185, 110) -> (-160, 110)
  line L2 (-160, 85) -> (-160, 110)
  line L3 (-135, 110) -> (-160, 110)
  line L4 (-160, 135) -> (-160, 110)
  line L5 (-184.8747, 107.5) -> (-160, 107.5)
  line L6 (-184.8747, 112.5) -> (-160, 112.5)
  line L7 (-162.5, 85.1253) -> (-162.5, 110)
  line L8 (-157.5, 85.1253) -> (-157.5, 110)
  line L9 (-135.1253, 107.5) -> (-160, 107.5)
  line L10 (-135.1253, 112.5) -> (-160, 112.5)
  line L11 (-162.5, 134.8747) -> (-162.5, 110)
  line L12 (-157.5, 134.8747) -> (-157.5, 110)
  circle C1 centre (-160, 110) radius 21
  circle C2 centre (-160, 110) radius 22.75
  circle C3 centre (-160, 110) radius 21
  circle C4 centre (-160, 110) radius 2.5
  circle C5 centre (-160, 110) radius 22.75
  circle C6 centre (-160, 110) radius 25
  point P6 (-160, 110)
  point P7 (-160, 110)
  point P8 (-185, 110)
  point P3 (-160, 110)
  point P9 (-160, 110)
  point P10 (-160, 85)
  point P5 (-160, 110)
  point P11 (-160, 110)
  point P12 (-135, 110)
  point P13 (-160, 135)
  point P14 (-160, 107.5)
  point P15 (-184.8747, 107.5)
  point P16 (-160, 112.5)
  point P17 (-184.8747, 112.5)
  point P18 (-162.5, 110)
  point P19 (-162.5, 85.1253)
  point P20 (-157.5, 110)
  point P21 (-157.5, 85.1253)
  point P22 (-135.1253, 107.5)
  point P23 (-135.1253, 112.5)
  point P24 (-162.5, 134.8747)
  point P25 (-157.5, 134.8747)
  tangent C1 C3
  concentric C3 C4
  concentric C4 C5
  concentric C4 C6
  coincident P6 P7
  coincident C6 P8
  horizontal L1
  coincident P3 P9
  coincident C6 P10
  perpendicular L1 L2
  coincident P5 P11
  coincident C6 P12
  perpendicular L2 L3
  coincident C6 P13
  perpendicular L3 L4
  coincident C4 P14
  coincident L2 P14
  coincident C6 P15
  tangent C4 L5
  coincident C4 P16
  coincident L4 P16
  coincident C6 P17
  tangent C4 L6
  coincident C4 P18
  coincident L1 P18
  coincident C6 P19
  tangent C4 L7
  coincident C4 P20
  coincident L3 P20
  coincident C6 P21
  tangent C4 L8
  coincident C6 P22
  horizontal L9
  coincident C6 P23
  parallel L9 L10
  coincident C6 P24
  perpendicular L10 L11
  coincident C6 P25
  vertical L12
  dimension "d294" diameter C4 = 5
  dimension "d297" diameter C6 = 50
extrude "Extruir31" new body sketch "Boceto34" profile of C4 along normal blind 10

design "pilares_anillos_baimax"
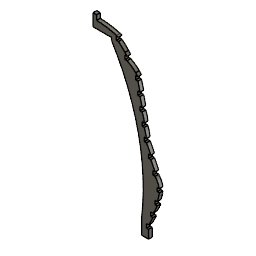
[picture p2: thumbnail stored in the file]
part number: 2026-07-06-18-36-34-739
parameter "d_1" = 112
parameter "d_1_int" = 108.5 (= "d_1 - 3.5 mm")
parameter "h_1" = -10
parameter "d_2" = 108.5
parameter "d_2_int" = 105 (= "d_2 - 3.5 mm")
parameter "h_2" = 10
parameter "h_3" = -20
parameter "h_4" = 20
parameter "h_5" = -30
parameter "h_6" = 30
parameter "h_7" = 40
parameter "d_3" = 105 (= "d_2_int")
parameter "d_3_int" = 101.5 (= "d_3 - 3.5 mm")
parameter "d_4" = 101.5 (= "d_3_int")
parameter "d_4_int" = 98 (= "d_4 - 3.5 mm")
parameter "d_5" = 98 (= "d_4_int")
parameter "d_5_int" = 94.5 (= "d_5 - 3.5 mm")
parameter "d_6" = 94.5 (= "d_5_int")
parameter "d_6_int" = 91 (= "d_6 - 3.5 mm")
parameter "d_7" = 91 (= "d_6_int")
parameter "d_7_int" = 87.5 (= "d_7 - 3.5 mm")
parameter "d_8" = 87.5 (= "d_7_int")
parameter "d_8_int" = 84 (= "d_8 - 3.5 mm")
parameter "h_8" = 50
parameter "h_9" = 60
parameter "h_10" = 70
parameter "h_11" = 110
parameter "h_12" = 120
parameter "h_13" = 130
parameter "h_14" = 140
parameter "h_15" = 80
parameter "d_9" = 84 (= "d_8_int")
parameter "d_9_int" = 80.5 (= "d_9 - 3.5 mm")
parameter "d_10" = 80.5 (= "d_9_int")
parameter "d_10_int" = 77 (= "d_10 - 3.5 mm")
parameter "d_11" = 77 (= "d_10_int")
parameter "d_11_int" = 73.5 (= "d_11 - 3.5 mm")
parameter "d_12" = 73.5 (= "d_11_int")
parameter "d_12_int" = 70 (= "d_12 - 3.5 mm")
parameter "d_13" = 70 (= "d_12_int")
parameter "d_13_int" = 66.5 (= "d_13 - 3.5 mm")
parameter "d_14" = 66.5 (= "d_13_int")
parameter "d_14_int" = 63 (= "d_14 - 3.5 mm")
parameter "d_15" = 63 (= "d_14_int")
parameter "d_15_int" = 59.5 (= "d_15 - 3.5 mm")
parameter "d_16" = 59.5 (= "d_15_int")
parameter "d_16_int" = 56 (= "d_16 - 3.5 mm")
parameter "h_16" = 160
parameter "h_17" = 170
parameter "h_18" = 180
parameter "h_19" = 90
parameter "h_20" = 200
parameter "d_17" = 56 (= "d_16_int")
parameter "d_17_int" = 52.5 (= "d_17 - 3.5 mm")
parameter "d_18" = 52.5 (= "d_17_int")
